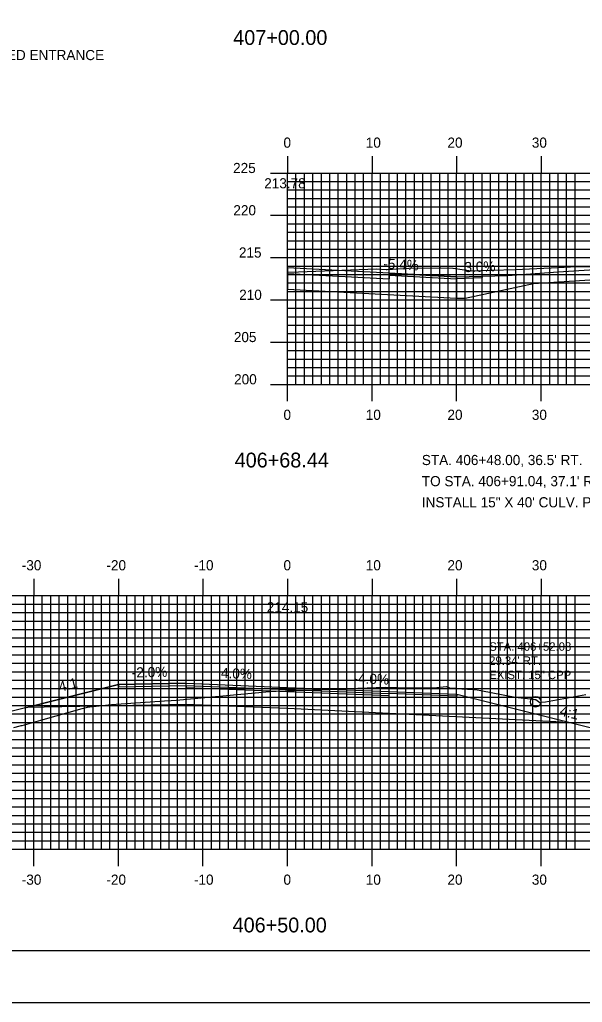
# Model space of a CAD drawing. Extents: x 852135 to 852479, y 364785 to 365005.
# Drawn here: x 852269.5 to 852336.1, y 364785.1 to 364901.4 of the extents above; entities that cross this region are included whole.
import ezdxf

# ---------------------------------------------------------------- set-up
doc = ezdxf.new("R2010")
doc.units = 0
for name, color, linetype in [('ANNOTATION', 7, 'Continuous'), ('BORDER', 7, 'Continuous'), ('D_Roadway_Centerline', 7, 'Continuous'), ('D_Roadway_Centerline_Text', 7, 'Continuous'), ('D_Roadway_Edge_Shoulder', 7, 'Continuous'), ('D_Roadway_FinishedGrade', 7, 'Continuous'), ('D_Roadway_Pavement', 7, 'Continuous'), ('D_Roadway_SlopeLines', 7, 'Continuous'), ('D_Roadway_SubGrade', 7, 'Continuous'), ('D_Text_Monospaced', 7, 'Continuous'), ('D_Text_Standard', 7, 'Continuous'), ('H_V ANNOTATION', 7, 'Continuous'), ('MAJOR', 7, 'Continuous'), ('MINOR', 7, 'Continuous'), ('PLOT BOUNDARY', 7, 'Continuous'), ('S_Roadway_Centerline', 7, 'Continuous'), ('S_Utilities_Pole_Power', 7, 'Continuous')]:
    doc.layers.add(name, color=color, linetype=linetype)

msp = doc.modelspace()

# ---------------------------------------------------------------- linework, layer by layer
at = {"layer": 'BORDER'}
msp.add_lwpolyline([(852151.62, 364791.23), (852471.62, 364791.23), (852471.62, 365001.23), (852151.62, 365001.23)], close=True, dxfattribs=at)
at = {"layer": 'D_Roadway_Centerline'}
msp.add_lwpolyline([(852270.35, 364819.99), (852281.22, 364822.7), (852289.22, 364822.86), (852301.22, 364822.38)], dxfattribs=at)
at = {"layer": 'D_Roadway_Edge_Shoulder'}
msp.add_line((852324.22, 364871.03), (852324.22, 364870.86), dxfattribs=at)
msp.add_lwpolyline([(852321.22, 364870.94), (852313.22, 364871.37), (852301.22, 364872.01)], dxfattribs=at)
msp.add_lwpolyline([(852289.22, 364822.86), (852281.22, 364822.7), (852281.22, 364822.45), (852289.22, 364822.61)], close=True, dxfattribs=at)
at = {"layer": 'D_Roadway_FinishedGrade'}
msp.add_lwpolyline([(852321.22, 364870.94), (852327.22, 364871.12), (852333.22, 364871.54), (852350.45, 364872.65)], dxfattribs=at)
at = {"layer": 'D_Roadway_Pavement'}
for p, q in [((852289.22, 364822.61), (852289.22, 364822.36)), ((852333.72, 364818.26), (852334.73, 364818.21))]:
    msp.add_line(p, q, dxfattribs=at)
for points in [[(852289.22, 364822.61), (852313.22, 364821.65), (852313.22, 364821.9)], [(852289.22, 364822.36), (852313.22, 364821.4), (852313.22, 364821.65)], [(852301.22, 364822.38), (852321.23, 364821.58), (852338.73, 364817.21)], [(852321.23, 364821.58), (852321.23, 364821.33), (852313.22, 364821.65)]]:
    msp.add_lwpolyline(points, dxfattribs=at)
at = {"layer": 'D_Roadway_SlopeLines'}
for points in [[(852281.22, 364822.7), (852244.53, 364813.53)], [(852321.22, 364821.38), (852321.23, 364821.38)]]:
    msp.add_lwpolyline(points, dxfattribs=at)
at = {"layer": 'D_Roadway_SubGrade'}
for p, q in [((852313.22, 364871.12), (852313.22, 364870.7)), ((852321.22, 364870.94), (852324.22, 364871.03)), ((852321.22, 364870.94), (852321.22, 364868.44)), ((852321.22, 364870.77), (852324.22, 364870.86)), ((852322.22, 364868.44), (852330.29, 364870.17)), ((852321.22, 364868.44), (852322.22, 364868.44))]:
    msp.add_line(p, q, dxfattribs=at)
for points in [[(852301.22, 364872.01), (852301.22, 364869.51), (852321.22, 364868.44)], [(852301.22, 364871.35), (852308.03, 364870.98), (852313.22, 364870.7)], [(852330.29, 364870.17), (852333.3, 364870.38), (852350.45, 364871.48)], [(852333.72, 364818.26), (852313.22, 364819.28), (852301.22, 364819.88), (852289.22, 364820.36), (852270.35, 364819.99), (852281.22, 364822.7), (852281.22, 364822.45), (852289.22, 364822.61), (852301.22, 364822.13)], [(852321.22, 364821.33), (852321.22, 364821.38), (852321.23, 364821.38)]]:
    msp.add_lwpolyline(points, dxfattribs=at)
msp.add_lwpolyline([(852313.22, 364871.37), (852321.22, 364870.94), (852321.22, 364870.69), (852313.22, 364871.12)], close=True, dxfattribs=at)
at = {"layer": 'MAJOR'}
for p, q in [((852301.22, 364885.24), (852301.22, 364883.23)), ((852311.22, 364885.24), (852311.22, 364883.23)), ((852321.22, 364885.24), (852321.22, 364883.23)), ((852331.22, 364885.24), (852331.22, 364883.23)), ((852299.21, 364883.23), (852301.22, 364883.23)), ((852301.22, 364883.23), (852441.22, 364883.23)), ((852301.22, 364858.23), (852301.22, 364883.23)), ((852301.22, 364858.23), (852301.22, 364883.23)), ((852301.22, 364883.23), (852441.22, 364883.23)), ((852311.22, 364858.23), (852311.22, 364883.23)), ((852321.22, 364858.23), (852321.22, 364883.23)), ((852331.22, 364858.23), (852331.22, 364883.23)), ((852299.21, 364878.23), (852301.22, 364878.23)), ((852301.22, 364878.23), (852441.22, 364878.23)), ((852299.21, 364873.23), (852301.22, 364873.23)), ((852301.22, 364873.23), (852441.22, 364873.23)), ((852299.21, 364868.23), (852301.22, 364868.23)), ((852301.22, 364868.23), (852441.22, 364868.23)), ((852299.21, 364863.23), (852301.22, 364863.23)), ((852301.22, 364863.23), (852441.22, 364863.23)), ((852299.21, 364858.23), (852301.22, 364858.23)), ((852301.22, 364858.23), (852441.22, 364858.23)), ((852301.22, 364858.23), (852441.22, 364858.23)), ((852301.22, 364856.23), (852301.22, 364858.23)), ((852311.22, 364856.23), (852311.22, 364858.23)), ((852321.22, 364856.23), (852321.22, 364858.23)), ((852331.22, 364856.23), (852331.22, 364858.23)), ((852271.22, 364835.24), (852271.22, 364833.23)), ((852281.22, 364835.24), (852281.22, 364833.23)), ((852291.22, 364835.24), (852291.22, 364833.23)), ((852301.22, 364835.24), (852301.22, 364833.23)), ((852311.22, 364835.24), (852311.22, 364833.23)), ((852321.22, 364835.24), (852321.22, 364833.23)), ((852331.22, 364835.24), (852331.22, 364833.23)), ((852161.22, 364833.23), (852441.22, 364833.23)), ((852161.22, 364833.23), (852441.22, 364833.23)), ((852271.22, 364803.23), (852271.22, 364833.23)), ((852281.22, 364803.23), (852281.22, 364833.23)), ((852291.22, 364803.23), (852291.22, 364833.23)), ((852301.22, 364803.23), (852301.22, 364833.23)), ((852311.22, 364803.23), (852311.22, 364833.23)), ((852321.22, 364803.23), (852321.22, 364833.23)), ((852331.22, 364803.23), (852331.22, 364833.23)), ((852161.22, 364828.23), (852441.22, 364828.23)), ((852161.22, 364823.23), (852441.22, 364823.23)), ((852161.22, 364818.23), (852441.22, 364818.23)), ((852161.22, 364813.23), (852441.22, 364813.23)), ((852161.22, 364808.23), (852441.22, 364808.23)), ((852161.22, 364803.23), (852441.22, 364803.23)), ((852161.22, 364803.23), (852441.22, 364803.23)), ((852271.22, 364801.23), (852271.22, 364803.23)), ((852281.22, 364801.23), (852281.22, 364803.23)), ((852291.22, 364801.23), (852291.22, 364803.23)), ((852301.22, 364801.23), (852301.22, 364803.23)), ((852311.22, 364801.23), (852311.22, 364803.23)), ((852321.22, 364801.23), (852321.22, 364803.23)), ((852331.22, 364801.23), (852331.22, 364803.23))]:
    msp.add_line(p, q, dxfattribs=at)
at = {"layer": 'MINOR'}
for p, q in [((852302.22, 364858.23), (852302.22, 364883.23)), ((852303.22, 364858.23), (852303.22, 364883.23)), ((852304.22, 364858.23), (852304.22, 364883.23)), ((852305.22, 364858.23), (852305.22, 364883.23)), ((852306.22, 364858.23), (852306.22, 364883.23)), ((852307.22, 364858.23), (852307.22, 364883.23)), ((852308.22, 364858.23), (852308.22, 364883.23)), ((852309.22, 364858.23), (852309.22, 364883.23)), ((852310.22, 364858.23), (852310.22, 364883.23)), ((852312.22, 364858.23), (852312.22, 364883.23)), ((852313.22, 364858.23), (852313.22, 364883.23)), ((852314.22, 364858.23), (852314.22, 364883.23)), ((852315.22, 364858.23), (852315.22, 364883.23)), ((852316.22, 364858.23), (852316.22, 364883.23)), ((852317.22, 364858.23), (852317.22, 364883.23)), ((852318.22, 364858.23), (852318.22, 364883.23)), ((852319.22, 364858.23), (852319.22, 364883.23)), ((852320.22, 364858.23), (852320.22, 364883.23)), ((852322.22, 364858.23), (852322.22, 364883.23)), ((852323.22, 364858.23), (852323.22, 364883.23)), ((852324.22, 364858.23), (852324.22, 364883.23)), ((852325.22, 364858.23), (852325.22, 364883.23)), ((852326.22, 364858.23), (852326.22, 364883.23)), ((852327.22, 364858.23), (852327.22, 364883.23)), ((852328.22, 364858.23), (852328.22, 364883.23)), ((852329.22, 364858.23), (852329.22, 364883.23)), ((852330.22, 364858.23), (852330.22, 364883.23)), ((852332.22, 364858.23), (852332.22, 364883.23)), ((852333.22, 364858.23), (852333.22, 364883.23)), ((852334.22, 364858.23), (852334.22, 364883.23)), ((852335.22, 364858.23), (852335.22, 364883.23)), ((852301.22, 364882.23), (852441.22, 364882.23)), ((852301.22, 364882.23), (852303.22, 364882.23)), ((852301.22, 364881.23), (852441.22, 364881.23)), ((852301.22, 364881.23), (852303.22, 364881.23)), ((852301.22, 364880.23), (852441.22, 364880.23)), ((852301.22, 364880.23), (852303.22, 364880.23)), ((852301.22, 364879.23), (852441.22, 364879.23)), ((852301.22, 364879.23), (852303.22, 364879.23)), ((852301.22, 364877.23), (852441.22, 364877.23)), ((852301.22, 364877.23), (852303.22, 364877.23)), ((852301.22, 364876.23), (852441.22, 364876.23)), ((852301.22, 364876.23), (852303.22, 364876.23)), ((852301.22, 364875.23), (852441.22, 364875.23)), ((852301.22, 364875.23), (852303.22, 364875.23)), ((852301.22, 364874.23), (852441.22, 364874.23)), ((852301.22, 364874.23), (852303.22, 364874.23)), ((852301.22, 364872.23), (852441.22, 364872.23)), ((852301.22, 364872.23), (852303.22, 364872.23)), ((852301.22, 364871.23), (852441.22, 364871.23)), ((852301.22, 364871.23), (852303.22, 364871.23)), ((852301.22, 364870.23), (852441.22, 364870.23)), ((852301.22, 364870.23), (852303.22, 364870.23)), ((852301.22, 364869.23), (852441.22, 364869.23)), ((852301.22, 364869.23), (852303.22, 364869.23)), ((852301.22, 364867.23), (852441.22, 364867.23)), ((852301.22, 364867.23), (852303.22, 364867.23)), ((852301.22, 364866.23), (852441.22, 364866.23)), ((852301.22, 364866.23), (852303.22, 364866.23)), ((852301.22, 364865.23), (852441.22, 364865.23)), ((852301.22, 364865.23), (852303.22, 364865.23)), ((852301.22, 364864.23), (852441.22, 364864.23)), ((852301.22, 364864.23), (852303.22, 364864.23)), ((852301.22, 364862.23), (852441.22, 364862.23)), ((852301.22, 364862.23), (852303.22, 364862.23)), ((852301.22, 364861.23), (852441.22, 364861.23)), ((852301.22, 364861.23), (852303.22, 364861.23)), ((852301.22, 364860.23), (852441.22, 364860.23)), ((852301.22, 364860.23), (852303.22, 364860.23)), ((852301.22, 364859.23), (852441.22, 364859.23)), ((852301.22, 364859.23), (852303.22, 364859.23)), ((852270.22, 364803.23), (852270.22, 364833.23)), ((852272.22, 364803.23), (852272.22, 364833.23)), ((852273.22, 364803.23), (852273.22, 364833.23)), ((852274.22, 364803.23), (852274.22, 364833.23)), ((852275.22, 364803.23), (852275.22, 364833.23)), ((852276.22, 364803.23), (852276.22, 364833.23)), ((852277.22, 364803.23), (852277.22, 364833.23)), ((852278.22, 364803.23), (852278.22, 364833.23)), ((852279.22, 364803.23), (852279.22, 364833.23)), ((852280.22, 364803.23), (852280.22, 364833.23)), ((852282.22, 364803.23), (852282.22, 364833.23)), ((852283.22, 364803.23), (852283.22, 364833.23)), ((852284.22, 364803.23), (852284.22, 364833.23)), ((852285.22, 364803.23), (852285.22, 364833.23)), ((852286.22, 364803.23), (852286.22, 364833.23)), ((852287.22, 364803.23), (852287.22, 364833.23)), ((852288.22, 364803.23), (852288.22, 364833.23)), ((852289.22, 364803.23), (852289.22, 364833.23)), ((852290.22, 364803.23), (852290.22, 364833.23)), ((852292.22, 364803.23), (852292.22, 364833.23)), ((852293.22, 364803.23), (852293.22, 364833.23)), ((852294.22, 364803.23), (852294.22, 364833.23)), ((852295.22, 364803.23), (852295.22, 364833.23)), ((852296.22, 364803.23), (852296.22, 364833.23)), ((852297.22, 364803.23), (852297.22, 364833.23)), ((852298.22, 364803.23), (852298.22, 364833.23)), ((852299.22, 364803.23), (852299.22, 364833.23)), ((852300.22, 364803.23), (852300.22, 364833.23)), ((852302.22, 364803.23), (852302.22, 364833.23)), ((852303.22, 364803.23), (852303.22, 364833.23)), ((852304.22, 364803.23), (852304.22, 364833.23)), ((852305.22, 364803.23), (852305.22, 364833.23)), ((852306.22, 364803.23), (852306.22, 364833.23)), ((852307.22, 364803.23), (852307.22, 364833.23)), ((852308.22, 364803.23), (852308.22, 364833.23)), ((852309.22, 364803.23), (852309.22, 364833.23)), ((852310.22, 364803.23), (852310.22, 364833.23)), ((852312.22, 364803.23), (852312.22, 364833.23)), ((852313.22, 364803.23), (852313.22, 364833.23)), ((852314.22, 364803.23), (852314.22, 364833.23)), ((852315.22, 364803.23), (852315.22, 364833.23)), ((852316.22, 364803.23), (852316.22, 364833.23)), ((852317.22, 364803.23), (852317.22, 364833.23)), ((852318.22, 364803.23), (852318.22, 364833.23)), ((852319.22, 364803.23), (852319.22, 364833.23)), ((852320.22, 364803.23), (852320.22, 364833.23)), ((852322.22, 364803.23), (852322.22, 364833.23)), ((852323.22, 364803.23), (852323.22, 364833.23)), ((852324.22, 364803.23), (852324.22, 364833.23)), ((852325.22, 364803.23), (852325.22, 364833.23)), ((852326.22, 364803.23), (852326.22, 364833.23)), ((852327.22, 364803.23), (852327.22, 364833.23)), ((852328.22, 364803.23), (852328.22, 364833.23)), ((852329.22, 364803.23), (852329.22, 364833.23)), ((852330.22, 364803.23), (852330.22, 364833.23)), ((852332.22, 364803.23), (852332.22, 364833.23)), ((852333.22, 364803.23), (852333.22, 364833.23)), ((852334.22, 364803.23), (852334.22, 364833.23)), ((852335.22, 364803.23), (852335.22, 364833.23)), ((852161.22, 364832.23), (852441.22, 364832.23)), ((852161.22, 364831.23), (852441.22, 364831.23)), ((852161.22, 364830.23), (852441.22, 364830.23)), ((852161.22, 364829.23), (852441.22, 364829.23)), ((852161.22, 364827.23), (852441.22, 364827.23)), ((852161.22, 364826.23), (852441.22, 364826.23)), ((852161.22, 364825.23), (852441.22, 364825.23)), ((852161.22, 364824.23), (852441.22, 364824.23)), ((852161.22, 364822.23), (852441.22, 364822.23)), ((852161.22, 364821.23), (852441.22, 364821.23)), ((852161.22, 364820.23), (852441.22, 364820.23)), ((852161.22, 364819.23), (852441.22, 364819.23)), ((852161.22, 364817.23), (852441.22, 364817.23)), ((852161.22, 364816.23), (852441.22, 364816.23)), ((852161.22, 364815.23), (852441.22, 364815.23)), ((852161.22, 364814.23), (852441.22, 364814.23)), ((852161.22, 364812.23), (852441.22, 364812.23)), ((852161.22, 364811.23), (852441.22, 364811.23)), ((852161.22, 364810.23), (852441.22, 364810.23)), ((852161.22, 364809.23), (852441.22, 364809.23)), ((852161.22, 364807.23), (852441.22, 364807.23)), ((852161.22, 364806.23), (852441.22, 364806.23)), ((852161.22, 364805.23), (852441.22, 364805.23)), ((852161.22, 364804.23), (852441.22, 364804.23))]:
    msp.add_line(p, q, dxfattribs=at)
at = {"layer": 'PLOT BOUNDARY'}
msp.add_lwpolyline([(852135.43, 364785.11), (852475.43, 364785.11), (852475.43, 365005.11), (852135.43, 365005.11)], close=True, dxfattribs=at)
at = {"layer": 'S_Roadway_Centerline'}
for points in [[(852301.22, 364871.51), (852302.52, 364871.56), (852311.73, 364871.9), (852312.88, 364871.81), (852313.01, 364871.82), (852315.56, 364871.99), (852319.29, 364872.03), (852319.36, 364872.02), (852320.78, 364871.98), (852320.81, 364871.97), (852322.94, 364871.68), (852325.43, 364871.73), (852328.13, 364871.81), (852332.4, 364872.03), (852334.7, 364872.14), (852337.73, 364872.18), (852347.79, 364872.52), (852349.29, 364872.58), (852350.66, 364872.66), (852357.9, 364873.1), (852371.01, 364873.85), (852378.05, 364874.33), (852386.25, 364874.92)], [(852268.85, 364817.64), (852269.61, 364817.81), (852269.71, 364817.85), (852269.85, 364817.88), (852272.33, 364818.57), (852276.93, 364819.88), (852277.57, 364820.04), (852277.64, 364820.07), (852277.84, 364820.09), (852279.33, 364820.25), (852279.99, 364820.32), (852280.01, 364820.32), (852280.1, 364820.33), (852280.39, 364820.34), (852286.66, 364820.78), (852287.45, 364820.84), (852288.05, 364820.88), (852299.08, 364821.88), (852299.68, 364821.93), (852299.72, 364821.93), (852299.77, 364821.93), (852299.86, 364821.94), (852312.76, 364822.39), (852315.61, 364822.34), (852318.88, 364822.35), (852320.01, 364822.47), (852320.36, 364822.32), (852321.04, 364822.27), (852321.11, 364822.23), (852323.22, 364822.11), (852323.65, 364822.08), (852324.07, 364822), (852328.15, 364821.23), (852329.95, 364821.04), (852330.48, 364820.94), (852330.6, 364820.96), (852331.06, 364820.59), (852331.16, 364820.64), (852331.73, 364820.66), (852336.51, 364821.53)]]:
    msp.add_lwpolyline(points, dxfattribs=at)
at = {"layer": 'S_Utilities_Pole_Power'}
msp.add_circle((852330.56, 364820.68), 0.625, dxfattribs=at)

# ---------------------------------------------------------------- texts
at = {"layer": 'ANNOTATION'}
for s, rotation, p in [('-5.4%', 356.9269, (852312.52, 364871.93)), ('3.0%', 1.7184, (852322.16, 364871.5)), ('-2.0%', 1.1458, (852282.82, 364823.54)), ('4.0%', 357.7094, (852293.33, 364823.5)), ('4:1', 14.0362, (852274.32, 364821.84)), ('-4.0%', 357.7094, (852309.01, 364822.87)), ('4:1', 345.9638, (852333.34, 364819.09))]:
    msp.add_text(s, height=1.2, rotation=rotation, dxfattribs=at).set_placement(p)
at = {"layer": 'D_Roadway_Centerline'}
for s, p in [('C', (852301.21, 364822.38)), ('L', (852301.22, 364822.38))]:
    msp.add_text(s, height=0.0146, dxfattribs=at).set_placement(p)
at = {"layer": 'D_Roadway_Centerline_Text'}
for s, p in [('213.78', (852298.46, 364881.42)), ('214.15', (852298.76, 364831.26))]:
    msp.add_text(s, height=1.2, dxfattribs=at).set_placement(p)
at = {"layer": 'D_Text_Monospaced'}
for s, p in [('STA. 406+52.08', (852325.07, 364826.71)), ("29.34' RT.", (852325.07, 364825.04)), ('EXIST. 15" CPP', (852325.07, 364823.36))]:
    msp.add_text(s, height=1, dxfattribs=at).set_placement(p)
at = {"layer": 'D_Text_Standard'}
for s, p in [('CONSTRUCT PAVED ENTRANCE', (852254.3, 364896.59)), ("STA. 406+48.00, 36.5' RT.", (852317.1, 364848.68)), ("TO STA. 406+91.04, 37.1' RT.", (852317.1, 364846.18)), ('INSTALL 15" X 40\' CULV. PIPE OPT. I', (852317.1, 364843.68))]:
    msp.add_text(s, height=1.2, dxfattribs=at).set_placement(p)
at = {"layer": 'H_V ANNOTATION'}
for s, height, p in [('407+00.00', 1.75, (852294.8, 364898.39)), ('0', 1.2, (852300.74, 364886.23)), ('10', 1.2, (852310.47, 364886.23)), ('20', 1.2, (852320.13, 364886.23)), ('30', 1.2, (852330.11, 364886.23)), ('225', 1.2, (852294.78, 364883.23)), ('220', 1.2, (852294.81, 364878.23)), ('215', 1.2, (852295.47, 364873.23)), ('210', 1.2, (852295.5, 364868.23)), ('205', 1.2, (852294.87, 364863.23)), ('200', 1.2, (852294.9, 364858.23)), ('0', 1.2, (852300.74, 364854.03)), ('10', 1.2, (852310.47, 364854.03)), ('20', 1.2, (852320.13, 364854.03)), ('30', 1.2, (852330.11, 364854.03)), ('406+68.44', 1.75, (852294.97, 364848.4)), ('-30', 1.2, (852269.79, 364836.23)), ('-20', 1.2, (852279.8, 364836.23)), ('-10', 1.2, (852290.15, 364836.23)), ('0', 1.2, (852300.74, 364836.23)), ('10', 1.2, (852310.47, 364836.23)), ('20', 1.2, (852320.13, 364836.23)), ('30', 1.2, (852330.11, 364836.23)), ('-30', 1.2, (852269.79, 364799.03)), ('-20', 1.2, (852279.8, 364799.03)), ('-10', 1.2, (852290.15, 364799.03)), ('0', 1.2, (852300.74, 364799.03)), ('10', 1.2, (852310.47, 364799.03)), ('20', 1.2, (852320.13, 364799.03)), ('30', 1.2, (852330.11, 364799.03)), ('406+50.00', 1.75, (852294.73, 364793.39))]:
    msp.add_text(s, height=height, dxfattribs=at).set_placement(p)
at = {"layer": 'MAJOR'}
msp.add_text('-', height=0.012, dxfattribs=at).set_placement((852301.21, 364858.23))
at = {"layer": 'S_Roadway_Centerline'}
for s in ['C', 'L']:
    msp.add_text(s, height=0.0146, dxfattribs=at).set_placement((852299.71, 364821.93))

doc.saveas('drawing.dxf')
